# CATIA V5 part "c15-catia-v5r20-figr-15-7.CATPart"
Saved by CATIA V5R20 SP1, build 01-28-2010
Part number: Part1
Bounding box of the stored display mesh (mm): x -50 to 50, y -32.5 to 33.5, z -52 to 1
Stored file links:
  D:\v5_r20\psrt_files_downloaded\c15\c15-catia-v5r20-figr-15-7.CATPart
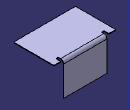
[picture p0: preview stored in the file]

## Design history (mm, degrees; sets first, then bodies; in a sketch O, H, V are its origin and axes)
SheetMetalParameters1: Thickness 1, BendRadius 4, KFactor 0.475772 {= log(min(100,max(20*SheetMetalParameters1.BendRadius,SheetMetalParameters1.Thickness)/SheetMetalParameters1.Thickness))/log(100)/2}, ReliefRadialLength 4, ReliefAxialLength 4, MinimumBendRadius 0
Body1 (main body)
  Sketch1 on xy-plane, origin (0, 0, 0), H (1, 0, 0), V (0, 1, 0)
    line L1 (-50, 32.5) -> (50, 32.5)
    line L2 (50, 32.5) -> (50, -32.5)
    line L3 (50, -32.5) -> (-50, -32.5)
    line L4 (-50, -32.5) -> (-50, 32.5)
    length L1 = 100
    length L2 = 65
    horizontal: L1 H, L3 H
    vertical: L2 V, L4 V
    symmetry: L4 L2 V, L1 L3 H
  Wall1: Thickness 1, Profile Sketch1
  d_NewWallOnEdge1: NewWallOnEdge_Edge edge [face of Wall1 | face of Wall1], NewWallOnEdge_Length 53, NewWallOnEdge_HeightLimitOffset 0, NewWallOnEdge_WidthOffset1 -15, NewWallOnEdge_WidthOffset2 -15, NewWallOnEdge_Angle 90, NewWallOnEdge_BendRadiusValue 4 {= SheetMetalParameters1.BendRadius}, NewWallOnEdge_BendTable SheetMetalParameters1, KFacteur 0.475772 {= log(min(100,max(20*d_NewWallOnEdge1.Radius,SheetMetalParameters1.Thickness)/SheetMetalParameters1.Thickness))/log(100)/2}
